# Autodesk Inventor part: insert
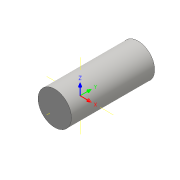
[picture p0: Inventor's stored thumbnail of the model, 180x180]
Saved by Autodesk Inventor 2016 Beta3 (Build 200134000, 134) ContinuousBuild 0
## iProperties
Created: 2016-03
Part Number: insert
Material: Generic
Document SubType Name: Modeling
Designer: Gaurav
Density: 1 g/cm^3
Appearance: Default
Author: Gaurav
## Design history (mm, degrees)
sketch "Sketch1"
  geometry: C1 r 5 at (0, 0); 1 further point
  constraints: 1 centre point, 1 coincident
  dimensions: "d0" = 10 diameter of C1
extrude "Extrusion1" new body sketch "Sketch1" distance "d1" = 25; taper "d2" = 0 deg
body "Solid1"
other parameters: "d3" = -1.444, "d4" = 9.061, "d5" = -1.996, "d6" = 0, "d7" = 0, "d8" = 0
